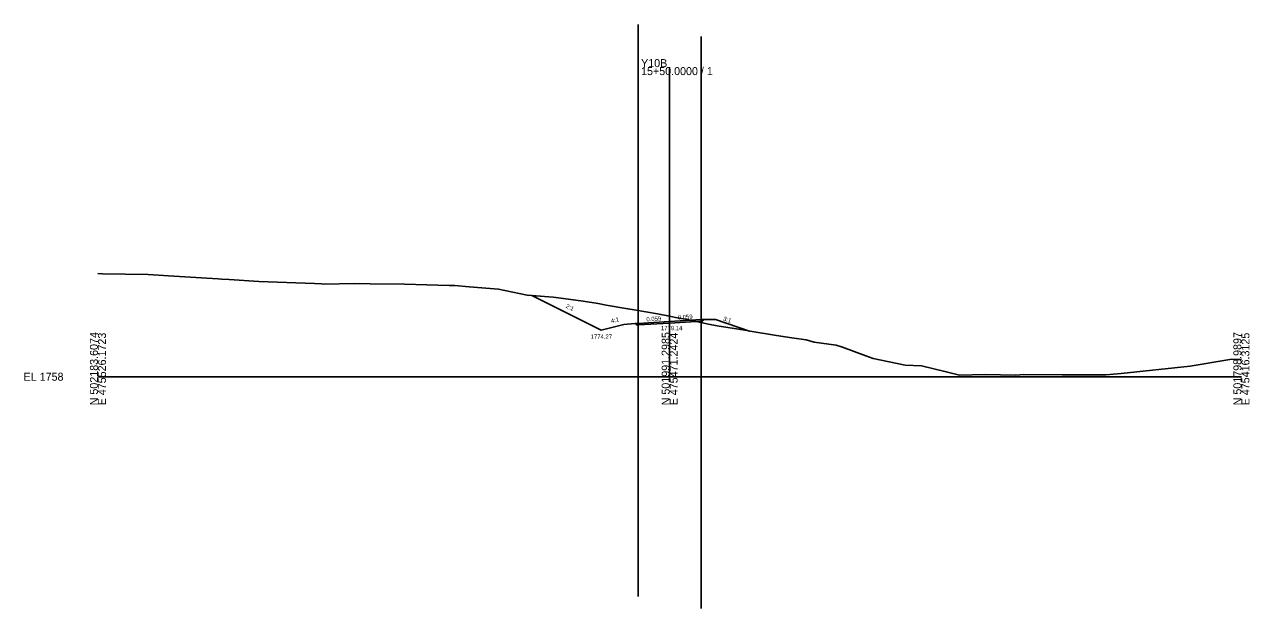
# Model space of a CAD drawing. Extents: x -26 to 1803, y -10 to 9558.
# Drawn here: x -25.7 to 402.8, y 5419 to 5623.1 of the extents above; entities that cross this region are included whole.
import ezdxf

# ---------------------------------------------------------------- set-up
doc = ezdxf.new("R2010")
doc.units = 0
for name, color, linetype in [('Exist Cross Section Cell', 7, 'Continuous'), ('Exist XS Center Line Elevation Label', 7, 'Continuous'), ('Exist XS Ground Line', 7, 'Continuous'), ('Prop XS Ditch Slope Text', 7, 'Continuous'), ('Prop XS Ditch Standard Text', 7, 'Continuous'), ('Prop XS Dump Level', 7, 'Continuous'), ('Prop XS Earthwork Shape', 7, 'Continuous'), ('Prop XS EOT Tick Mark', 7, 'Continuous'), ('Prop XS Finish Grade', 7, 'Continuous'), ('Prop XS Finish Grade Earthwork', 7, 'Continuous'), ('Prop XS Finish Grade Pavement', 7, 'Continuous'), ('Prop XS Hydro Typical Ditch Data', 7, 'Continuous'), ('Prop XS Pvmt Edge Slope', 7, 'Continuous'), ('Prop XS SE Text', 7, 'Continuous'), ('Prop XS Shoulder Borrow Shape', 7, 'Continuous'), ('Prop XS Side Slope Text', 7, 'Continuous'), ('Prop XS Subgrade Earthwork', 7, 'Continuous'), ('Scratch_Level_2', 7, 'Continuous')]:
    doc.layers.add(name, color=color, linetype=linetype)

msp = doc.modelspace()

# ---------------------------------------------------------------- linework, layer by layer
at = {"layer": 'Exist Cross Section Cell'}
for p, q in [((200, 5500), (200, 5608.26)), ((0, 5500), (200, 5500)), ((200, 5500), (400, 5500))]:
    msp.add_line(p, q, dxfattribs=at)
at = {"layer": 'Exist XS Ground Line'}
msp.add_lwpolyline([(0, 5536.09), (1.62, 5536.02), (9.51, 5535.91), (17.55, 5535.73), (24.68, 5535.22), (38.1, 5534.43), (42.04, 5534.19), (43.24, 5534.12), (45.93, 5533.98), (56.23, 5533.34), (75.71, 5532.59), (78.2, 5532.47), (79.29, 5532.41), (89.67, 5532.58), (95.25, 5532.52), (107.25, 5532.31), (122.87, 5531.9), (124.84, 5531.88), (129.86, 5531.4), (140.1, 5530.56), (142.36, 5530.11), (150.19, 5528.52), (159.23, 5527.77), (164.57, 5527.13), (169.69, 5526.42), (174.97, 5525.55), (177.78, 5525.08), (185.37, 5523.79), (187.61, 5523.39), (195.77, 5521.96), (200, 5521.14), (202.05, 5520.75), (206.18, 5519.97), (213.6, 5518.43), (216.58, 5517.82), (224.03, 5516.6), (226.98, 5516.12), (228.16, 5515.94), (237.38, 5514.46), (242.72, 5513.65), (247.78, 5512.87), (250.6, 5512.09), (258.19, 5511.09), (260.45, 5510.35), (268.59, 5507.36), (271.22, 5506.4), (282.44, 5504.09), (288.09, 5503.78), (296.76, 5501.73), (301.39, 5500.55), (310.4, 5500.78), (321.05, 5500.6), (323.86, 5500.73), (337.33, 5500.64), (352.54, 5500.7), (357.95, 5501.11), (382.08, 5503.7), (395.94, 5505.98), (400, 5506.1)], dxfattribs=at)
at = {"layer": 'Prop XS Dump Level'}
for p, q in [((200, 5519.31), (211, 5519.96)), ((189, 5518.67), (200, 5519.31))]:
    msp.add_line(p, q, dxfattribs=at)
at = {"layer": 'Prop XS Earthwork Shape'}
for points in [[(159.23, 5527.77), (164.57, 5527.13), (169.69, 5526.42), (174.97, 5525.55), (177.78, 5525.08), (185.37, 5523.79), (187.61, 5523.39), (195.77, 5521.96), (200, 5521.14), (202.05, 5520.75), (206.18, 5519.97), (209.32, 5519.32), (200, 5518.77), (189, 5518.13), (188.42, 5518.09), (187.93, 5518.58), (184, 5518.27), (176, 5516.27), (151.76, 5528.39)], [(211.51, 5519.45), (212.02, 5519.96), (216, 5519.96), (227.95, 5515.97), (226.98, 5516.12), (224.03, 5516.6), (216.58, 5517.82), (213.6, 5518.43), (209.32, 5519.32), (211, 5519.42)]]:
    msp.add_lwpolyline(points, close=True, dxfattribs=at)
at = {"layer": 'Prop XS EOT Tick Mark'}
for p, q in [((189, 5518.67), (189, 5519.67)), ((211, 5519.96), (211, 5520.96))]:
    msp.add_line(p, q, dxfattribs=at)
at = {"layer": 'Prop XS Finish Grade'}
for p, q in [((211, 5519.96), (212.02, 5519.96)), ((189, 5518.67), (187.93, 5518.58))]:
    msp.add_line(p, q, dxfattribs=at)
at = {"layer": 'Prop XS Finish Grade Earthwork'}
for p, q in [((176, 5516.27), (151.76, 5528.39)), ((212.02, 5519.96), (216, 5519.96)), ((227.95, 5515.97), (216, 5519.96)), ((184, 5518.27), (176, 5516.27)), ((187.93, 5518.58), (184, 5518.27))]:
    msp.add_line(p, q, dxfattribs=at)
at = {"layer": 'Prop XS Finish Grade Pavement'}
for p, q in [((200, 5519.31), (211, 5519.96)), ((189, 5518.67), (200, 5519.31))]:
    msp.add_line(p, q, dxfattribs=at)
at = {"layer": 'Prop XS Hydro Typical Ditch Data'}
for p, q in [((176, 5516.27), (151.76, 5528.39)), ((184, 5518.27), (176, 5516.27))]:
    msp.add_line(p, q, dxfattribs=at)
at = {"layer": 'Prop XS Pvmt Edge Slope'}
for p, q in [((211, 5519.96), (211.51, 5519.45)), ((189, 5518.67), (188.42, 5518.09))]:
    msp.add_line(p, q, dxfattribs=at)
at = {"layer": 'Prop XS Shoulder Borrow Shape'}
for points in [[(211, 5519.96), (211.51, 5519.45), (212.02, 5519.96)], [(189, 5518.67), (187.93, 5518.58), (188.42, 5518.09)]]:
    msp.add_lwpolyline(points, close=True, dxfattribs=at)
at = {"layer": 'Prop XS Subgrade Earthwork'}
for p, q in [((211.51, 5519.45), (212.02, 5519.96)), ((188.42, 5518.09), (187.93, 5518.58)), ((189, 5518.13), (188.42, 5518.09)), ((200, 5518.77), (189, 5518.13)), ((211, 5519.42), (200, 5518.77)), ((211, 5519.42), (211.51, 5519.45))]:
    msp.add_line(p, q, dxfattribs=at)
at = {"layer": 'Scratch_Level_2'}
for p, q in [((189, 5623.15), (189, 5423.15)), ((211, 5618.97), (211, 5418.97))]:
    msp.add_line(p, q, dxfattribs=at)

# ---------------------------------------------------------------- texts
at = {"layer": 'Exist Cross Section Cell'}
for s, p in [('Y10B', (190, 5608.26)), ('15+50.0000 / 1', (190, 5605.46)), ('EL 1758', (-26, 5498.6))]:
    msp.add_text(s, height=2.8, dxfattribs=at).set_placement(p)
for s, p in [('N 502183.6074', (0, 5490)), ('E 475526.1723', (2.8, 5490)), ('N 501991.2985', (200, 5490)), ('E 475471.2424', (202.8, 5490)), ('N 501798.9897', (400, 5490)), ('E 475416.3125', (402.8, 5490))]:
    msp.add_text(s, height=2.8, rotation=90, dxfattribs=at).set_placement(p)
at = {"layer": 'Exist XS Center Line Elevation Label'}
msp.add_text('1779.14', height=1.5, dxfattribs=at).set_placement((196.96, 5516.28))
at = {"layer": 'Prop XS Ditch Slope Text'}
msp.add_text('4:1', height=1.5, rotation=14.0362, dxfattribs=at).set_placement((179.64, 5518.72))
at = {"layer": 'Prop XS Ditch Standard Text'}
msp.add_text('1774.27', height=1.5, dxfattribs=at).set_placement((172.36, 5513.27))
at = {"layer": 'Prop XS Dump Level'}
for p in [(216, 5519.92), (184, 5518.23)]:
    msp.add_text('Case1', height=0.04, dxfattribs=at).set_placement(p)
at = {"layer": 'Prop XS SE Text'}
for p in [(191.9, 5519.34), (202.9, 5519.98)]:
    msp.add_text('0.059', height=1.5, rotation=3.3644, dxfattribs=at).set_placement(p)
at = {"layer": 'Prop XS Side Slope Text'}
for s, rotation, p in [('2:1', 333.4349, (163.49, 5524.2)), ('3:1', 341.5651, (218.56, 5519.69))]:
    msp.add_text(s, height=1.5, rotation=rotation, dxfattribs=at).set_placement(p)

doc.saveas('drawing.dxf')
